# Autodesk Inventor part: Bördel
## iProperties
Created: 2010-06
Part Number: Bördel
Material: 1.0038
Document SubType Name: Modeling
Designer: LL
Stock Number: =<Type>
Density: 7.86 g/cm^3
Author: LL
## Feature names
1. Bezeichnung1 [Tagging]
